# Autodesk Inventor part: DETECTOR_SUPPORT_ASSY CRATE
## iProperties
Shininess: 64.0
Length Units: 11272
Angle Units: 11279
Time Units: 11290
Mass Units: 11286
Length Display Precision: 3
Angle Display Precision: 2
Compacted: True
Part Number: DETECTOR_SUPPORT_ASSY CRATE
Document SubType Name: Modeling
Created: 2004-08
Designer: John Blackburn
Manufacturer: Standard
Standards Organization: Custom
Density: 0.0
Volumn: 0.0
Area: 0.0
PropertySet Name: Model Information
Control State: 0
Master: False
Checked Out: False
Author: John Blackburn
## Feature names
1. ExtrusionBlind1
